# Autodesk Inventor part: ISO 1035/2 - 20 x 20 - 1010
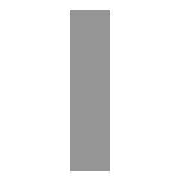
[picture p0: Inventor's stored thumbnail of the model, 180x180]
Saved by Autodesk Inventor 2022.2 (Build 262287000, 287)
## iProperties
IsCustomPart: 1
Created: 2025-02
Part Number: ISO 1035/2 - 20 x 20 - 1010
Material: Acciaio, Dolce
Description: Barre in acciaio laminate a caldo - Parte 2: barre quadre
Document SubType Name: Modeling
Standard: ISO 1035/2
Designer: 18907419
Standard Revision: First edition 1980-10-15
Standards Organization: ISO
Language: it-IT
Size Designation: 20x 20
Categories: <MemberInstance><Categories><Category DisplayName="Forme strutturali" InternalName="089c4875-fa83-4c05-b084-43b9cc11f5ed" Mnemonic="GRDR"><CategoryParameter Dis
Stock Number: 20x 20
Density: 7.85 g/cm^3
Appearance: Semilucidato
_CCFamilyMember: 168
_CCFamilyDisplayName: ISO 1035/2 - 1980 - Barre in acciaio laminate a caldo - Parte 2: barre quadre
_FrameMemberDoc: Frame Member File
_Version: 15.0.0
_GetPNFromCC: 1
G_L: 1010,000 mm
G_W: 20,000 mm
G_H: 20,000 mm
+374DB05E-BE82-4ECA-88F7-B26F20248773+CUTDETAIL1: Angolo retto 45,00 gr
+D4C4440D-AAA4-41A5-A4A6-87245F75C31E+CUTDETAIL2: Angolo retto 45,00 gr
Author: 18907419
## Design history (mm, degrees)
node "Piano iniziale"
node "Piano finale"
sketch "Schizzo"
  geometry: L1 (10, -10)-(-10, -10); L2 (-10, -10)-(-10, 10); L3 (-10, 10)-(10, 10); L4 (10, 10)-(10, -10); L5 (-6, 0)-(8, 0); L6 (0, -30)-(0, 40); L7 (0, 54)-(0, -44) reference; L8 (-14, 0)-(14, 0) reference
  constraints: 12 end point, 2 collinear, 2 parallel, 1 horizontal, 1 perpendicular
  dimensions: "d0" = 20 distance between parallel lines of L3 L1 (= G_W); "d1" = 20 distance between parallel lines of L4 L2 (= G_H); "d4" = 10 distance between parallel lines of L6 L4 (= 0.5 x d1); "d5" = 10 distance between parallel lines of L5 L3 (= 0.5 x d0)
extrude "Corpo" new body sketch "Schizzo" stored distance "d2" = 1010 (= G_L); taper "d3" = 0 deg
node "Driven Length"
  sketch "Sketch3"
    geometry: L1 (0, 0)-(10, 0) reference
    constraints: 2 end point, 1 horizontal
  workplane "Work Plane3"
  sketch "Sketch4"
    geometry: L1 (-2, -10)-(12, -10) reference; L2 (-2, 1000)-(12, 1000) reference
    dimensions: "d9" = 1010 dimension on L1 L2 (derived)
node "Piano di lavoro4"
feature "Divisione1"
node "Piano di lavoro5"
feature "Divisione2"
body "Solid1"
other parameters: "G_W" = 20 [user parameter; used in 1 equation term], "G_H" = 20 [user parameter; used in 1 equation term], "G_L" = 1010 (= d9) [user parameter; used in 1 equation term], "G_OFFSET_END" = 0 [user parameter; used in 1 equation term], "d8" = 90 deg
